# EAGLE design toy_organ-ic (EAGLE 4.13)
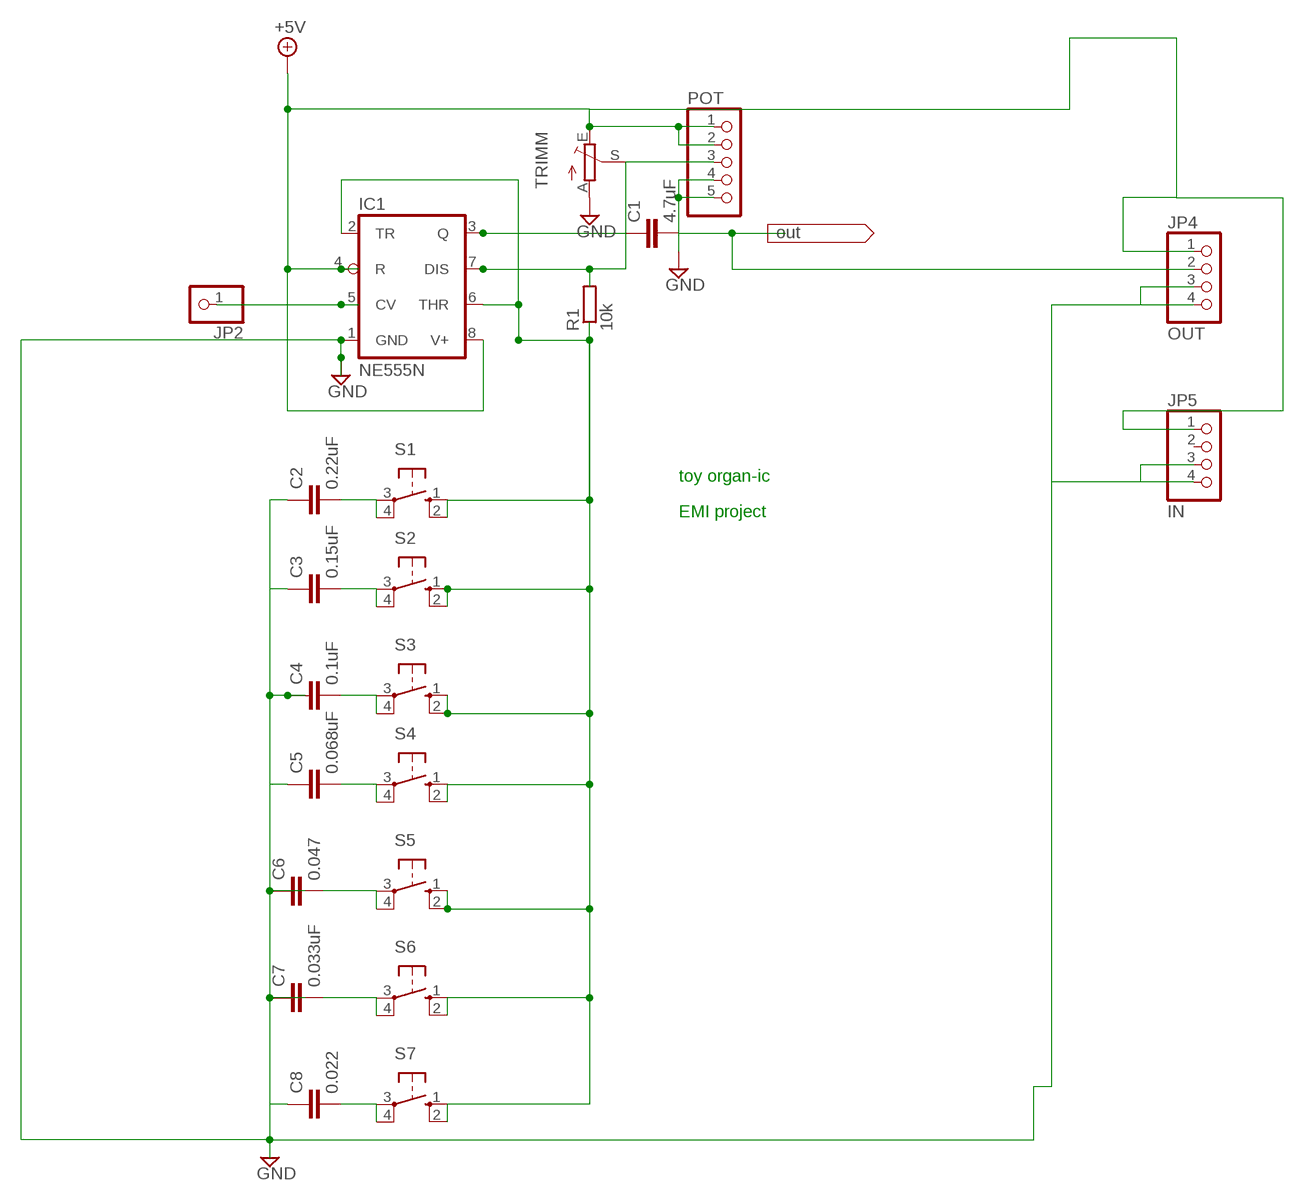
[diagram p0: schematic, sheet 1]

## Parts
C1  4.7uF  C-EU025-025X050  [C025-025X050]
C2  0.22uF  C-EU025-024X044  [C025-024X044]
C3  0.15uF  C-EU025-024X044  [C025-024X044]
C4  0.1uF  C-EU025-024X044  [C025-024X044]
C5  0.068uF  C-EU025-024X044  [C025-024X044]
C6  0.047  C-EU025-024X044  [C025-024X044]
C7  0.033uF  C-EU025-024X044  [C025-024X044]
C8  0.022  C-EU025-024X044  [C025-024X044]
IC1  NE555N  [DIL08]
JP2  PINHD-1X1  [1X01]
JP4  OUT  PINHD-1X4  [1X04]
JP5  IN  PINHD-1X4  [1X04]
POT  PINHD-1X5  [1X05]
R1  10k  R-EU_0204/5  [0204/5]
S1  10-XX  [B3F-10XX]
S2  10-XX  [B3F-10XX]
S3  10-XX  [B3F-10XX]
S4  10-XX  [B3F-10XX]
S5  10-XX  [B3F-10XX]
S6  10-XX  [B3F-10XX]
S7  10-XX  [B3F-10XX]
TRIMM  TRIM_EU-LI10  [LI10]

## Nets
+5V: IC1.4(R) IC1.8(V+) JP4.1 JP5.1 POT.1 POT.2 TRIMM.E
GND: C2.1 C3.1 C4.1 C5.1 C6.1 C7.1 C8.1 IC1.1(GND) JP4.3 JP4.4 JP5.3 JP5.4 POT.4 POT.5 TRIMM.A
N$1: C1.1 IC1.3(Q)
N$2: C1.2 JP4.2
N$3: IC1.7(DIS) POT.3 R1.2 TRIMM.S
N$5: IC1.5(CV) JP2.1
N$6: IC1.2(TR) IC1.6(THR) R1.1 S1.1(S) S1.2(S1) S2.1(S) S2.2(S1) S3.1(S) S3.2(S1) S4.1(S) S4.2(S1) S5.1(S) S5.2(S1) S6.1(S) S6.2(S1) S7.1(S) S7.2(S1)
N$11: C2.2 S1.3(P) S1.4(P1)
N$12: C3.2 S2.3(P) S2.4(P1)
N$13: C4.2 S3.3(P) S3.4(P1)
N$14: C5.2 S4.3(P) S4.4(P1)
N$15: C6.2 S5.3(P) S5.4(P1)
N$16: C7.2 S6.3(P) S6.4(P1)
N$17: C8.2 S7.3(P) S7.4(P1)
Unconnected: JP5.2

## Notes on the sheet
- toy organ-ic
- EMI project

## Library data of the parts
C1-C8 = rcl:C-EU: CAPACITOR, European symbol
IC1 = linear:*555: TIMER
JP2 = pinhead:PINHD-1X1: PIN HEADER
JP4 JP5 = pinhead:PINHD-1X4: PIN HEADER
POT = pinhead:PINHD-1X5: PIN HEADER
R1 = rcl:R-EU_: RESISTOR, European symbol
S1-S7 = switch-omron:10-XX: OMRON SWITCH
TRIMM = pot:TRIM_EU-: POTENTIOMETER

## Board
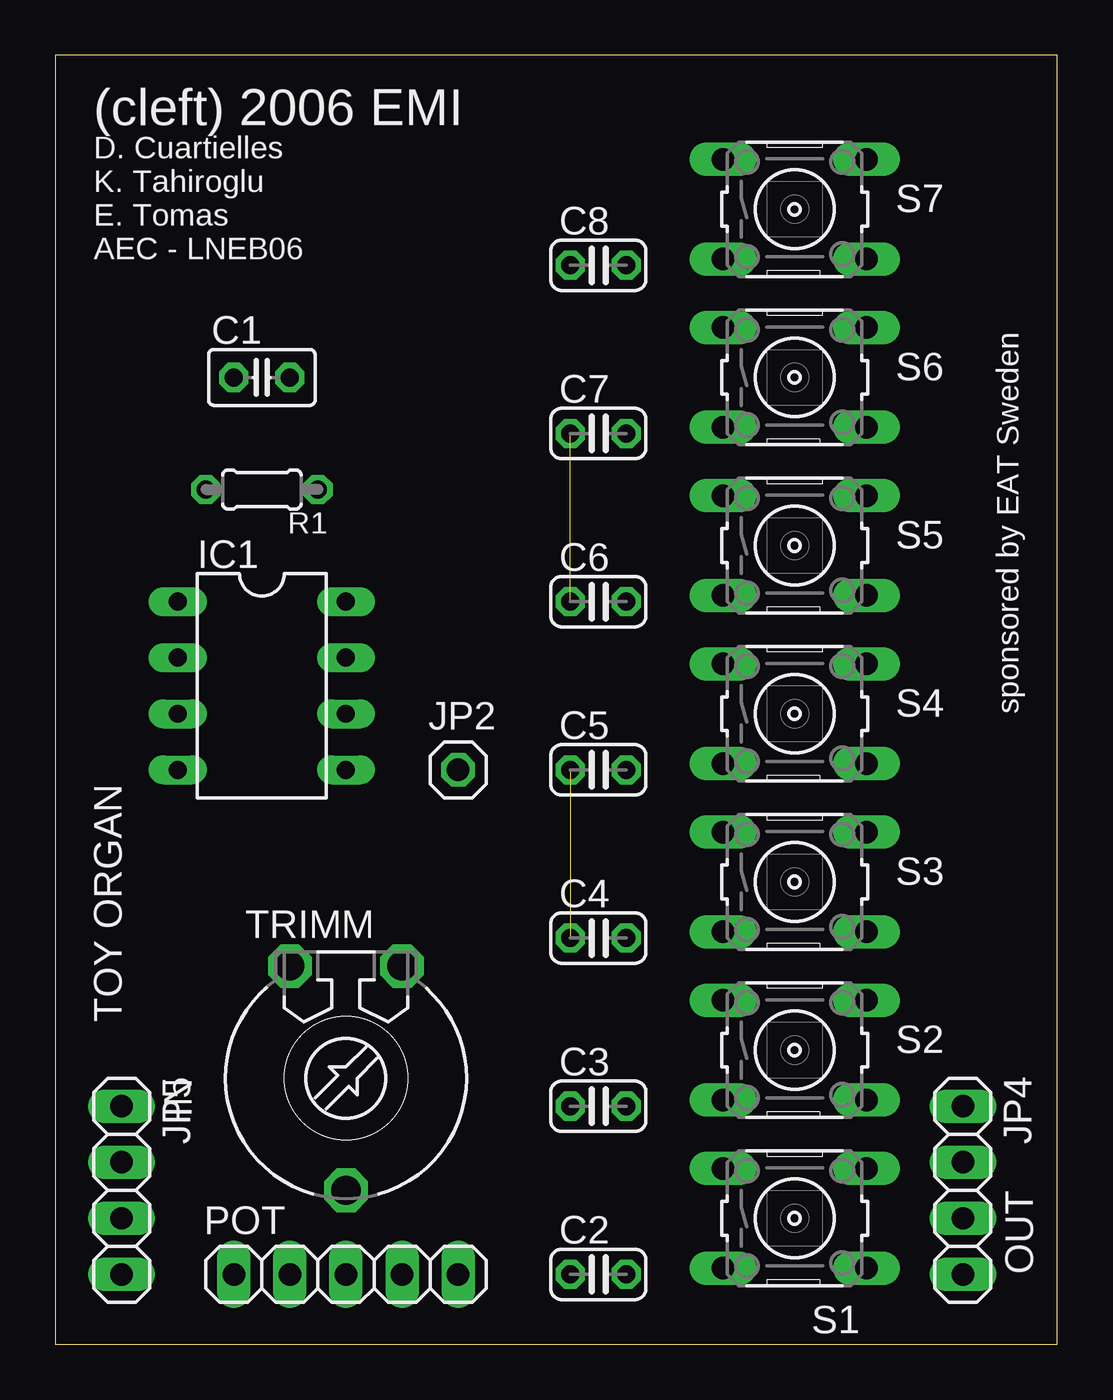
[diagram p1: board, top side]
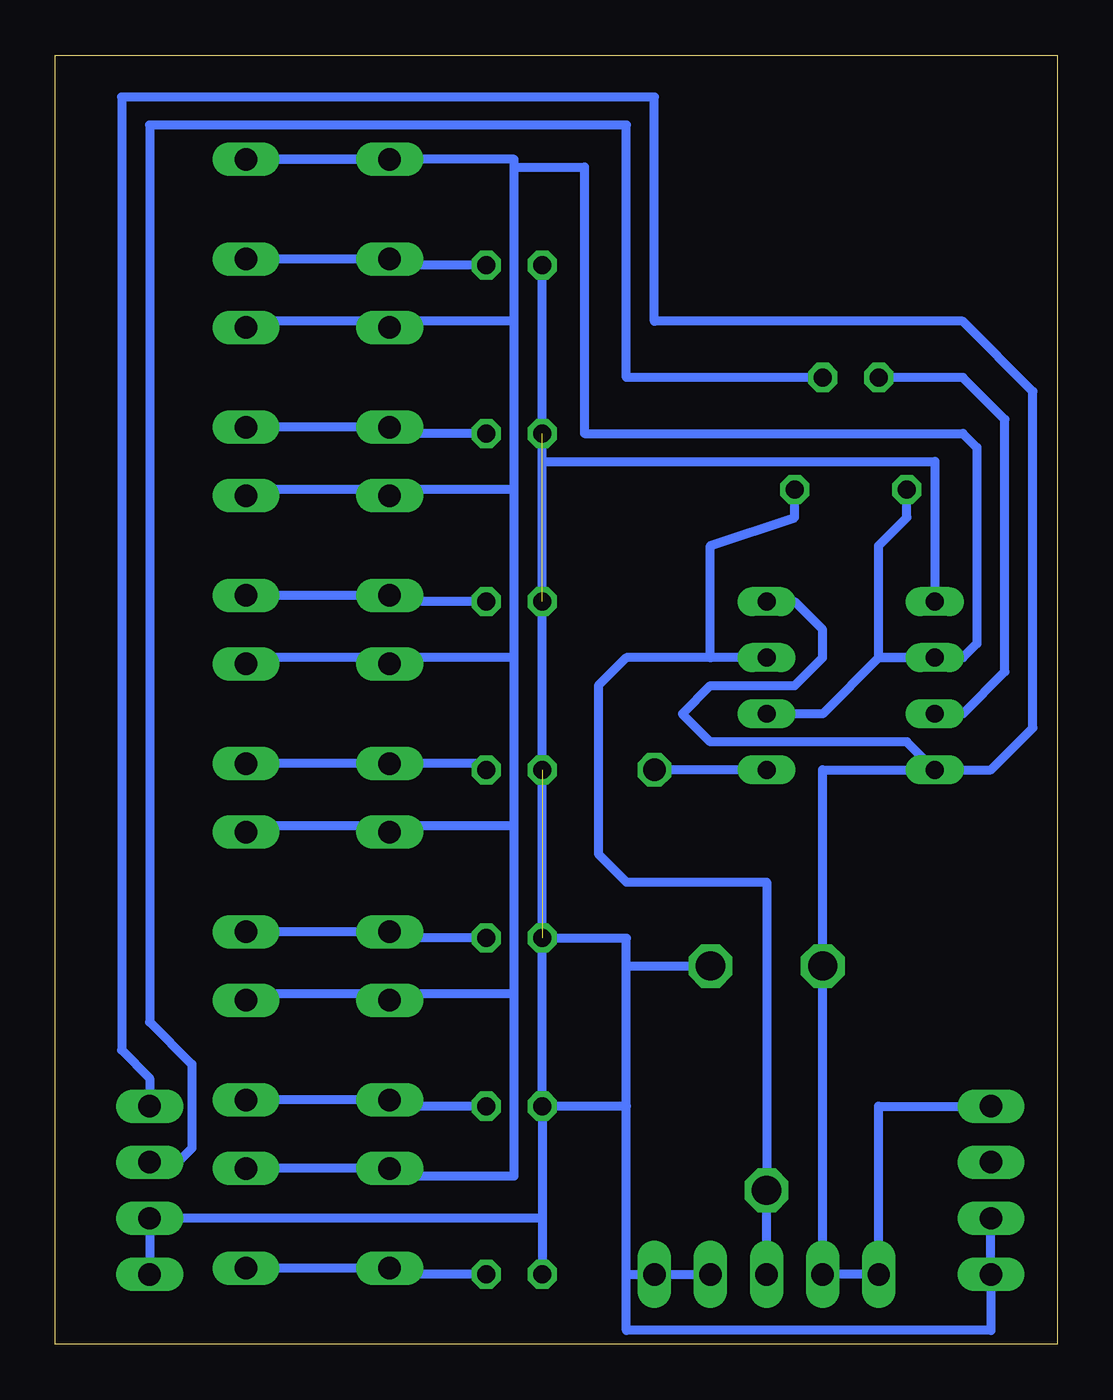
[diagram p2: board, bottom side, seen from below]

Size 45.39 x 58.41 mm. Coordinates in mm from the lower left corner, seen from the top.
Outline: 0,0 45.39,0 45.39,58.41 0,58.41 0,0
Copper layers (1*16): Top 0.035mm / dielectric 1.5mm / Bottom 0.035mm
Design rules "default": minimum track width 10mil, minimum drill 24mil, track to track 8mil, track to pad 8mil, pad to pad 8mil, via to via 8mil, smd to smd 8mil, copper to edge 40mil, drill to drill 8mil, minimum pad ring 10mil, minimum via ring 8mil, stop-mask expansion 4mil, vias tented up to drill 0mil, thermal gap 10mil

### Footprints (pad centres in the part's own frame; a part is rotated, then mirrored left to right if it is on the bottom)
C025-025X050 = drill 0.813 octagon: 1 -1.27,0; 2 1.27,0
C025-024X044 = drill 0.813 octagon: 1 -1.27,0; 2 1.27,0
DIL08 = drill 0.813 long: 1 -3.81,-3.81; 2 -1.27,-3.81; 3 1.27,-3.81; 4 3.81,-3.81; 5 3.81,3.81; 6 1.27,3.81; 7 -1.27,3.81; 8 -3.81,3.81
1X01 = drill 1.016 octagon: 1 0,0
1X04 = drill 1.016 long: 1 -3.81,0; 2 -1.27,0; 3 1.27,0; 4 3.81,0
1X05 = drill 1.016 long: 1 -5.08,0; 2 -2.54,0; 3 0,0; 4 2.54,0; 5 5.08,0
0204/5 = drill 0.813 octagon: 1 -2.54,0; 2 2.54,0
B3F-10XX = drill 1.016 long: 1 -3.251,2.261; 2 3.251,2.261; 3 -3.251,-2.261; 4 3.251,-2.261
LI10 = drill 1.321 octagon: A -2.54,-5.08; E 2.54,-5.08; S 0,5.08

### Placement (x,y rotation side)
C1  9.36,43.81 0 top
C2  24.6,3.17 0 top
C3  24.6,10.79 0 top
C4  24.6,18.41 0 top
C5  24.6,26.03 0 top
C6  24.6,33.65 0 top
C7  24.6,41.27 0 top
C8  24.6,48.89 0 top
IC1  9.36,29.84 270 top
JP2  18.25,26.03 0 top
JP4  41.11,6.98 270 top
JP5  3.01,6.98 270 top
POT  13.17,3.17 0 top
R1  9.36,38.73 0 top
S1  33.49,5.71 0 top
S2  33.49,13.33 0 top
S3  33.49,20.95 0 top
S4  33.49,28.57 0 top
S5  33.49,36.19 0 top
S6  33.49,43.81 0 top
S7  33.49,51.43 0 top
TRIMM  13.17,12.06 180 top

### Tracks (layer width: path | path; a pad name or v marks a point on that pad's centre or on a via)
+5V
  Bottom 0.406: JP5.1 8.09,10.79 POT.1 POT.2 TRIMM.E 10.63,26.03 IC1.4 | IC1.8 11.9,33.65 10.63,32.38 10.63,31.11 11.9,29.84 15.71,29.84 16.98,28.57 15.71,27.3 6.82,27.3 IC1.4 | JP4.1 41.11,12.06 42.38,13.33 42.38,56.51 18.25,56.51 18.25,46.35 4.28,46.35 1.1,43.17 1.1,27.93 3.01,26.03 IC1.4
GND  (3 unrouted)
  Bottom 0.406: C3.1 C4.1 | C3.1 23.33,5.71 | 23.33,5.71 C2.1 | C4.1 23.33,40 | 23.33,40 C8.1 | JP5.3 JP5.4 3.01,0.63 19.52,0.63 19.52,3.17 | 19.52,3.17 19.52,10.79 | 19.52,10.79 19.52,17.14 | 19.52,17.14 19.52,18.41 C4.1 | 19.52,17.14 TRIMM.A | 19.52,10.79 C3.1 | POT.4 POT.5 19.52,3.17 | 23.33,5.71 JP4.3 JP4.4 | IC1.1 5.55,40 23.33,40
N$1
  Bottom 0.406: IC1.3 4.28,28.57 2.38,30.47 2.38,41.91 4.28,43.81 C1.1
N$2
  Bottom 0.406: C1.2 19.52,43.81 19.52,55.24 41.11,55.24 41.11,14.6 39.2,12.7 39.2,8.88 39.84,8.25 JP4.2
N$3
  Bottom 0.406: POT.3 TRIMM.S 13.17,20.95 19.52,20.95 20.79,22.22 20.79,29.84 19.52,31.11 15.71,31.11 | R1.2 11.9,37.46 15.71,36.19 15.71,31.11 | IC1.7 15.71,31.11
N$5
  Bottom 0.406: IC1.5 JP2.1
N$6
  Bottom 0.406: S1.2 36.74,8.17 36.66,8.25 36.39,7.97 S1.1 30.31,7.97 30.31,7.62 24.6,7.62 24.6,15.87 | S7.1 36.39,53.69 36.66,53.97 36.74,53.89 S7.2 24.6,53.69 24.6,53.34 | 24.6,15.87 24.6,23.49 | 24.6,23.49 24.6,31.11 | 24.6,31.11 24.6,38.73 | 24.6,38.73 24.6,46.35 | 24.6,46.35 24.6,53.34 | 8.09,31.11 IC1.2 | R1.1 6.82,37.46 8.09,36.19 8.09,31.11 | 24.6,46.35 29.96,46.35 S6.1 30.31,46.15 30.31,46.35 36.46,46.35 S6.2 | 24.6,38.73 29.96,38.73 S5.1 30.31,38.53 30.31,38.73 36.46,38.73 S5.2 | 24.6,31.11 29.96,31.11 S4.1 30.31,30.91 30.31,31.11 36.46,31.11 S4.2 | 24.6,23.49 29.96,23.49 S3.1 30.31,23.29 30.31,23.49 36.46,23.49 S3.2 | 24.6,15.87 29.96,15.87 S2.1 30.31,15.51 30.31,15.24 30.95,15.87 36.46,15.87 S2.2 | IC1.6 10.63,28.57 8.09,31.11 | 8.09,31.11 4.28,31.11 3.64,31.74 3.64,40.63 4.28,41.27 21.42,41.27 21.42,53.34 24.6,53.34
N$11
  Bottom 0.406: C2.2 30.31,3.17 30.24,3.25 S1.3 36.39,3.45 36.66,3.17 36.74,3.25 S1.4
N$12
  Bottom 0.406: C3.2 30.31,10.79 30.24,10.87 S2.3 36.39,11.07 36.66,10.79 36.74,10.87 S2.4
N$13
  Bottom 0.406: C4.2 30.31,18.41 30.24,18.49 S3.3 36.39,18.69 36.66,18.41 36.74,18.49 S3.4
N$14
  Bottom 0.406: C5.2 26.15,26.31 S4.3 36.31,26.31 36.66,26.66 36.74,26.59 S4.4
N$15
  Bottom 0.406: C6.2 30.31,33.65 30.24,33.73 S5.3 36.39,33.93 36.66,33.65 36.74,33.73 S5.4
N$16
  Bottom 0.406: C7.2 30.31,41.27 30.24,41.35 S6.3 36.39,41.55 36.66,41.27 36.74,41.35 S6.4
N$17
  Bottom 0.406: C8.2 29.68,48.89 29.96,49.17 S7.3 30.24,48.97 30.31,48.89 30.59,49.17 S7.4

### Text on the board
tPlace: (cleft) 2006 EMI | D. Cuartielles | K. Tahiroglu | E. Tomas | AEC - LNEB06 | sponsored by EAT Sweden | TOY ORGAN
